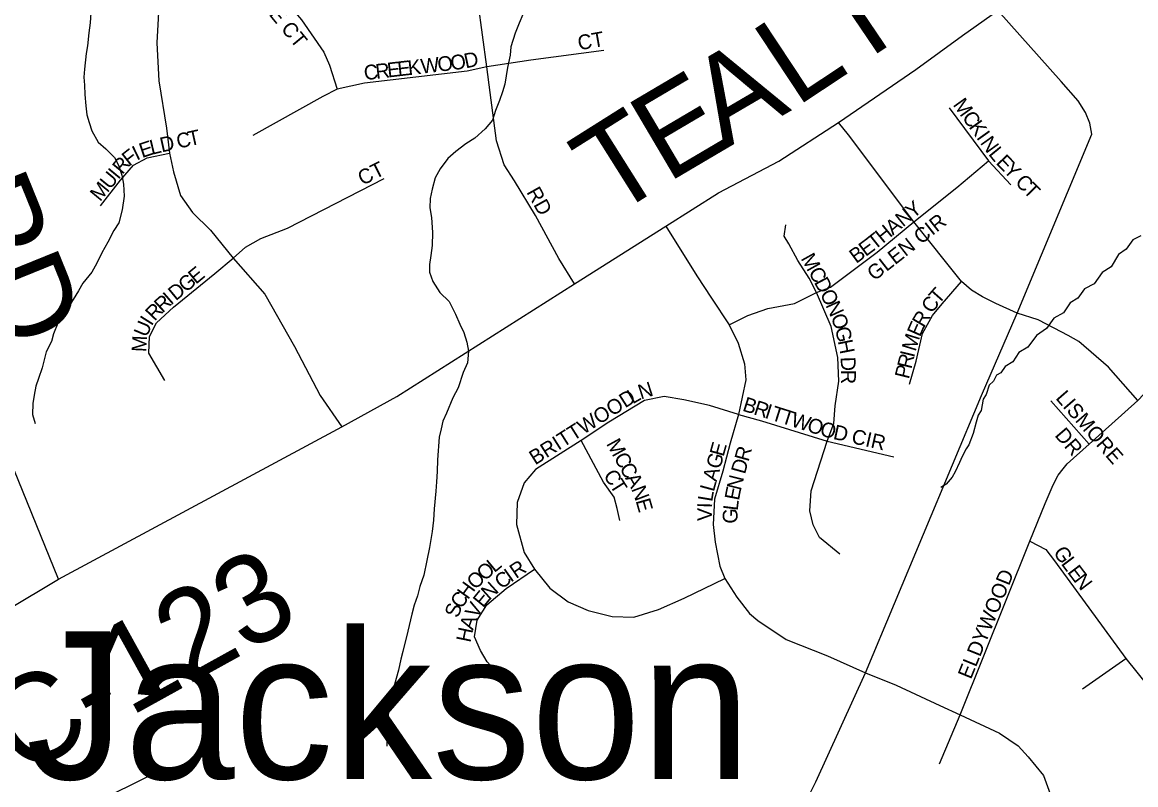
# Model space of a CAD drawing. Extents: x 1310247 to 1664935, y 235267 to 584339.
# Drawn here: x 1471939 to 1475707, y 405864 to 408445 of the extents above; entities that cross this region are included whole.
import ezdxf

# ---------------------------------------------------------------- set-up
doc = ezdxf.new("R2010")
doc.units = 0
for name, color, linetype in [('GM_X_County_Road', 7, 'Continuous'), ('GM_X_County_Road_Text', 7, 'Continuous'), ('GM_X_Minor_Lake_Text', 7, 'Continuous'), ('GM_X_Minor_River', 7, 'Continuous'), ('GM_X_Township_Road', 7, 'Continuous'), ('GM_X_Township_Road_Text', 7, 'Continuous'), ('GM_X_Township_Subdivision', 7, 'Continuous'), ('GM_X_Township_Subdivision_Text', 7, 'Continuous')]:
    doc.layers.add(name, color=color, linetype=linetype)

msp = doc.modelspace()

# ---------------------------------------------------------------- linework, layer by layer
at = {"layer": 'GM_X_County_Road'}
msp.add_lwpolyline([(1469618.3, 405075.7), (1469723.7, 405193), (1469936.4, 405367.3), (1470080.1, 405482.1), (1470194.3, 405541.7), (1470349.5, 405630.1), (1470505.2, 405715.2), (1470749, 405849.7), (1470814, 405888), (1471061, 406020.1), (1471335.2, 406154.1), (1471420.3, 406197.5), (1471890.1, 406457.8), (1472061.8, 406560), (1473020.6, 407075.3), (1473206.7, 407178.8), (1473808.4, 407559.6), (1474117, 407754.9), (1474295.5, 407867.9), (1474499.6, 407974.6), (1474701.1, 408105.8), (1474962.6, 408285.4), (1475121.3, 408399.8), (1475239.9, 408484.7)], dxfattribs=at)
at = {"layer": 'GM_X_Minor_River'}
for points in [[(1472171.6, 408477.1), (1472169, 408443), (1472164.4, 408409), (1472159.7, 408364.9), (1472155.2, 408338.9), (1472150.3, 408286.7), (1472147.8, 408258.6), (1472149.4, 408232.5), (1472150.9, 408200.3), (1472154.2, 408162.1), (1472157.7, 408132), (1472165.3, 408105.7), (1472174.9, 408077.4), (1472196.3, 408038.9), (1472222, 408016.3), (1472251.7, 407987.7), (1472265.3, 407961.4), (1472276.7, 407927), (1472282.2, 407896.8), (1472283.6, 407856.6), (1472276.8, 407810.5), (1472266, 407766.5), (1472249.5, 407740.7), (1472228.8, 407700.9), (1472208.1, 407665.1), (1472191.4, 407629.3), (1472174.9, 407599.4), (1472144.1, 407561.8), (1472129.6, 407536), (1472088.3, 407468.4), (1472059.5, 407426.7), (1472044.9, 407390.8), (1472038.4, 407364.8), (1472019.7, 407329), (1472006.8, 407275), (1471994.1, 407239.1), (1471985.7, 407213.1), (1471979.1, 407183.1), (1471974.6, 407155.1), (1471974, 407116.9), (1471983.5, 407086.6)], [(1473632.9, 408471.6), (1473620.3, 408441.7), (1473607.7, 408407.8), (1473592.9, 408361.9), (1473590.4, 408333.8), (1473581.7, 408291.8), (1473572.7, 408235.7), (1473564.2, 408209.7), (1473553.7, 408179.8), (1473541.1, 408145.9), (1473530.5, 408113.9), (1473505.9, 408084.2), (1473471.2, 408052.7), (1473440.8, 408033.1), (1473406.2, 408007.6), (1473379.7, 407984), (1473353, 407948.3), (1473336.5, 407918.5)], [(1473336.5, 407918.5), (1473325.8, 407880.5), (1473319.2, 407848.5), (1473318.7, 407816.4), (1473324.2, 407784.1), (1473327.3, 407733.9), (1473326.6, 407689.7), (1473322, 407655.6), (1473317.5, 407625.6), (1473317, 407599.5), (1473328.5, 407567.2), (1473352, 407530.6), (1473383.6, 407499.9), (1473405, 407457.4), (1473420.4, 407423), (1473434, 407394.6), (1473443.5, 407362.3), (1473449, 407332.1), (1473446.3, 407292), (1473431.8, 407260.1), (1473414.8, 407208.1), (1473396.2, 407174.3), (1473375.2, 407122.5), (1473362.7, 407094.6), (1473356.3, 407068.6), (1473349.8, 407040.6), (1473344.5, 406964.4), (1473343.8, 406924.2), (1473341.2, 406890.1), (1473338.7, 406858), (1473333.6, 406797.9), (1473331, 406759.7), (1473326.3, 406721.7), (1473317.4, 406667.6), (1473308.6, 406623.6), (1473297.7, 406573.5), (1473285, 406535.6), (1473276.5, 406503.6), (1473265.9, 406471.7), (1473257.3, 406441.7), (1473244.3, 406383.7), (1473227.1, 406315.7), (1473220.7, 406289.7), (1473212, 406251.7), (1473199.1, 406203.7), (1473190.6, 406173.8), (1473179.9, 406131.8), (1473177.2, 406095.7), (1473172.7, 406065.6), (1473172.3, 406039.5), (1473173.5, 405995.3)], [(1475723.9, 407722), (1475697.6, 407708.4), (1475675, 407676.7), (1475648.6, 407659.1), (1475623.8, 407617.3), (1475593.4, 407597.8), (1475566.6, 407560.1), (1475534.2, 407542.6), (1475511.6, 407510.8), (1475485.2, 407495.2), (1475462.6, 407461.5), (1475430.2, 407444), (1475405.5, 407408.2), (1475371, 407384.8), (1475342.2, 407345.1), (1475311.8, 407327.5), (1475291.2, 407295.8), (1475264.8, 407280.2), (1475250.4, 407258.3), (1475236.2, 407250.5), (1475225.8, 407230.6), (1475211.6, 407216.8), (1475201, 407184.9), (1475190.7, 407169), (1475184, 407131), (1475173.7, 407115.1), (1475167.3, 407091.1), (1475156.6, 407053.1), (1475141.9, 407015.2), (1475133.6, 407001.3), (1475119.2, 406975.4), (1475110.8, 406955.5), (1475096.2, 406923.6), (1475085.9, 406905.7), (1475065.4, 406882), (1475047.1, 406870.3)]]:
    msp.add_lwpolyline(points, dxfattribs=at)
at = {"layer": 'GM_X_Township_Road'}
for points in [[(1474001.2, 405348.9), (1474008.6, 405355.7), (1474087.4, 405426.5), (1474143.2, 405476.4), (1474257.7, 405560.6), (1474396.4, 405661.3), (1474492.3, 405732.9), (1474542.3, 405773.9), (1474601.5, 405828.6), (1474624.4, 405874.5), (1474792.2, 406243.1), (1475185.1, 407181.4), (1475305.4, 407460.8), (1475558.2, 408066.7), (1475552.2, 408102.9), (1475537.1, 408139.9), (1475512.2, 408179.2), (1475454.8, 408244.9), (1475239.9, 408484.7)], [(1472061.8, 406560), (1471790.3, 407226.9), (1471622.4, 407631), (1471514.1, 407906), (1471466.6, 408026.5), (1471422.8, 408130), (1471380.2, 408195.7), (1471301.1, 408289.4), (1471220.7, 408351.5), (1471027.5, 408456.4)]]:
    msp.add_lwpolyline(points, dxfattribs=at)
at = {"layer": 'GM_X_Township_Subdivision'}
for points in [[(1473808.4, 407559.6), (1473754.4, 407645.4), (1473675.9, 407790.9), (1473604.6, 407908.8), (1473569.7, 407962.6), (1473543.5, 408044), (1473523.1, 408207), (1473511.5, 408294.3), (1473482.4, 408511), (1473467.8, 408591), (1473451.8, 408674), (1473421.3, 408748.1), (1473387.8, 408822.3), (1473360.2, 408879), (1473313.6, 408937.2), (1473121.6, 409140.9), (1472898.3, 409373.6), (1472689.5, 409589), (1472650.3, 409644.2), (1472628.5, 409683.5), (1472619.7, 409760.6), (1472632, 409830.4)], [(1472898.3, 409373.6), (1472806.3, 409287.1), (1472675.4, 409161.6), (1472560.7, 409056.6), (1472513.1, 409009), (1472463.4, 408939.8), (1472432.4, 408839.8), (1472419.2, 408773.9), (1472411.7, 408685.8), (1472394.2, 408375.5), (1472400.9, 408246.8), (1472427.3, 408086.6), (1472437.7, 408001.8), (1472450.9, 407938.7), (1472474.4, 407858.6), (1472514.9, 407801.1), (1472576.2, 407740.9), (1472653.4, 407646.6), (1472759.9, 407525.1), (1472860.7, 407347), (1472947.3, 407181.9), (1473020.6, 407075.3)], [(1472720.1, 408644.9), (1472884.5, 408452.8), (1472959.7, 408343.8), (1472978.9, 408299.4), (1473004.4, 408218.4)], [(1473907.2, 408349.5), (1473659.8, 408316.1), (1473511.5, 408294.3), (1473444.7, 408279.5), (1473097.8, 408239), (1473004.4, 408218.4), (1472956.8, 408193.6), (1472719.6, 408062)], [(1475076.3, 408155), (1475209.2, 407976), (1475284.2, 407894.3)], [(1475305.4, 407460.8), (1475233.6, 407492.9), (1475189.1, 407515.5), (1475151.6, 407538.1), (1475118, 407567), (1474956.1, 407770), (1474735.4, 408064.4), (1474701.1, 408105.8)], [(1472203.7, 407823.7), (1472272.2, 407910.4), (1472315.9, 407960.8), (1472362.2, 407985.6), (1472437.7, 408001.8)], [(1474331.7, 407420.4), (1474394, 407452), (1474462, 407476.2), (1474551.9, 407492.7), (1474627, 407530.4), (1474674.6, 407548.6), (1474832.6, 407666.3), (1474956.1, 407770), (1475101.9, 407886.1), (1475209.2, 407976)], [(1472421.7, 407233), (1472368, 407325.4), (1472369.8, 407381.9), (1472393.4, 407428.1), (1472450.9, 407480.8), (1472591.2, 407594.8), (1472653.4, 407646.6), (1472694.9, 407683.4), (1472746.7, 407713.5), (1472837.1, 407748.4), (1473164, 407916.1)], [(1474117, 407754.9), (1474221.7, 407586.5), (1474271.4, 407511), (1474331.7, 407420.4), (1474361.7, 407359), (1474382.8, 407288.8), (1474388, 407234.4), (1474362.9, 407117), (1474335, 407020), (1474309.7, 406926.1), (1474282, 406830.9), (1474277.2, 406745.4), (1474283.8, 406685.8), (1474300.1, 406604.5), (1474316.9, 406562.4), (1474357.3, 406499.2), (1474400, 406443.8), (1474428.3, 406419.7), (1474523.9, 406356.2), (1474664.6, 406300.9), (1474792.2, 406243.1), (1474896.1, 406201), (1475044.7, 406132.6), (1475113.1, 406101), (1475245.9, 406039.2), (1475309.1, 405995.8), (1475343.2, 405959), (1475394.5, 405895.8), (1475435.3, 405784)], [(1474705.9, 406644.3), (1474637.3, 406700.9), (1474615.6, 406744.2), (1474604.8, 406791.2), (1474608.4, 406858.6), (1474662.6, 407027.3), (1474685.5, 407087.5), (1474690.3, 407146.5), (1474702.3, 407230.8), (1474698.7, 407310.3), (1474676.5, 407415.3), (1474627, 407530.4), (1474601.5, 407578.6), (1474563.6, 407638.7), (1474532.8, 407695.5), (1474517.8, 407721.5), (1474522.6, 407759.4)], [(1474941.3, 407220.5), (1474963.8, 407297.6), (1474986.1, 407391.3), (1475019.7, 407453), (1475051.8, 407491.7), (1475118, 407567)], [(1475713.9, 407165.3), (1475615.4, 407277.3), (1475514.7, 407364), (1475478, 407384.3), (1475431.1, 407409.3), (1475376.4, 407437.4), (1475305.4, 407460.8)], [(1475113.1, 406101), (1475348.7, 406688.8), (1475400.8, 406816.5), (1475427.2, 406879.7), (1475445, 406911.8), (1475461.1, 406933.4), (1475475.6, 406950.2), (1475549.9, 407017.3), (1475713.9, 407165.3), (1475793.9, 407249.4), (1475880, 407324.9)], [(1474362.9, 407117), (1474265.1, 407147.7), (1474178.4, 407167), (1474111, 407177.8), (1474044.8, 407164.5), (1473924.3, 407091.1), (1473830.4, 407029.7), (1473676.2, 406930.9), (1473637.7, 406886.4), (1473613.6, 406820.1), (1473611.2, 406745.4), (1473637.7, 406650.3), (1473672.6, 406593.7), (1473724.4, 406529.9), (1473787, 406482.9), (1473854.5, 406454), (1473935.2, 406433.5), (1474008.6, 406431.1), (1474091.7, 406457.6), (1474179.6, 406496.1), (1474316.9, 406562.4)], [(1475420.1, 407163.3), (1475549.9, 407017.3)], [(1474362.9, 407117), (1474441, 407095.9), (1474662.6, 407027.3), (1474889, 406974.3)], [(1473961.7, 406758.7), (1473952, 406799.6), (1473942.4, 406838.2), (1473906.3, 406888.8), (1473830.4, 407029.7)], [(1475348.7, 406688.8), (1475402.8, 406660.7), (1475432.6, 406622.7), (1475673.2, 406291.3), (1475818.3, 406111.8), (1476048.3, 405789.8), (1476182.4, 405651.7), (1476253.5, 405568.7), (1476314.4, 405461.3)], [(1473557, 406232.4), (1473512.4, 406280.6), (1473489.6, 406319.1), (1473469.2, 406364.6), (1473478.7, 406421.5), (1473511.2, 406473.3), (1473576.3, 406528.6), (1473672.6, 406593.7)], [(1475527.2, 406188.7), (1475673.2, 406291.3)], [(1475043.4, 405935.6), (1475113.1, 406101)], [(1472060.1, 405705.4), (1472050.6, 405736.3), (1472362.5, 405891.2)]]:
    msp.add_lwpolyline(points, dxfattribs=at)

# ---------------------------------------------------------------- texts
at = {"layer": 'GM_X_County_Road_Text'}
for s, rotation, p in [('T', 34.1193, (1474747.4, 408281.4)), ('L', 33.4852, (1474557.2, 408155.6)), ('A', 30.3684, (1474314.3, 408012.7)), ('E', 30.5433, (1474121.3, 407898.8)), ('T', 32.2303, (1473933.5, 407780.3)), ('C-123', 28.9506, (1471933.1, 405888.5))]:
    msp.add_text(s, height=300, rotation=rotation, dxfattribs=at).set_placement(p)
at = {"layer": 'GM_X_Minor_Lake_Text'}
msp.add_text('Jackson', height=499.99, rotation=0.0001, dxfattribs=at).set_placement((1471951.6, 405883.5))
at = {"layer": 'GM_X_Township_Road_Text'}
msp.add_text('RD', height=300, rotation=292.0722, dxfattribs=at).set_placement((1471661.1, 407857.4))
at = {"layer": 'GM_X_Township_Subdivision_Text'}
for s, rotation, p in [('RIDGE CT', 309.4798, (1472665.8, 408600)), ('CT', 10.0138, (1473823.4, 408349.9)), ('E', 6.5151, (1473176.7, 408257.8)), ('E', 6.5214, (1473211.6, 408261.8)), ('K', 6.5401, (1473246.6, 408265.7)), ('W', 6.5203, (1473290.3, 408270.8)), ('O', 6.5285, (1473347.2, 408277.3)), ('O', 7.04, (1473391.4, 408282.3)), ('D', 12.1856, (1473439.9, 408288.5)), ('C', 6.5226, (1473098, 408248.7)), ('R', 6.532, (1473137.3, 408253.2)), ('M', 305.5948, (1475086.7, 408165.7)), ('C', 305.5828, (1475117.4, 408122.7)), ('K', 305.5758, (1475140.5, 408090.5)), ('L', 13.6519, (1472377.1, 407996)), ('D', 12.5359, (1472411, 408004.3)), ('C', 12.5325, (1472466.9, 408016.7)), ('T', 12.5318, (1472505.5, 408025.3)), ('I', 305.5792, (1475166.1, 408054.7)), ('N', 305.5993, (1475178.9, 408036.8)), ('F', 38.0667, (1472301.2, 407956)), ('I', 25.7245, (1472326.5, 407976.2)), ('E', 18.5127, (1472344.8, 407985.1)), ('L', 309.2603, (1475206.6, 407998.3)), ('R', 50.5498, (1472278.1, 407927.4)), ('CT', 26.565, (1473090.4, 407891.4)), ('E', 313.7851, (1475231.8, 407967.8)), ('Y', 314.1072, (1475256.3, 407942.2)), ('U', 50.5414, (1472236.1, 407876.5)), ('I', 50.5438, (1472264.1, 407910.4)), ('M', 50.5466, (1472202.6, 407835.7)), ('C', 314.098, (1475296.1, 407901.1)), ('T', 314.0918, (1475323.7, 407872.6)), ('RD', 299.361, (1473644, 407870)), ('Y', 39.1956, (1474953.3, 407778)), ('GLEN CIR', 38.1104, (1474822.6, 407567.4)), ('N', 39.2164, (1474919.2, 407750.2)), ('H', 39.1847, (1474851, 407694.6)), ('A', 39.2164, (1474885.1, 407722.4)), ('E', 36.6217, (1474793.2, 407650.2)), ('T', 38.3611, (1474822.8, 407672.2)), ('B', 36.3308, (1474761.1, 407626.6)), ('M', 299.1891, (1474572.3, 407645.8)), ('E', 39.6212, (1472526.6, 407556.3)), ('C', 299.1728, (1474598.1, 407599.7)), ('D', 39.7076, (1472458.8, 407500.2)), ('G', 39.5985, (1472492.6, 407528.3)), ('D', 298.0121, (1474617.3, 407565.4)), ('R', 42.4403, (1472413.5, 407459.4)), ('I', 41.0708, (1472442.5, 407485.9)), ('O', 295.1674, (1474637.6, 407527.1)), ('T', 48.5185, (1475039.9, 407488.1)), ('R', 46.46, (1472386.9, 407431.4)), ('N', 294.5019, (1474656.3, 407487.4)), ('C', 55.2726, (1475018.3, 407456.8)), ('I', 57.6193, (1472376.7, 407414.8)), ('O', 290.5919, (1474674.2, 407448.2)), ('R', 59.6492, (1474990.3, 407408.6)), ('U', 67.1716, (1472360.6, 407376.2)), ('G', 282.6473, (1474689.1, 407408.8)), ('E', 66.3192, (1474976.9, 407377.7)), ('M', 87.3577, (1472359.2, 407328)), ('H', 281.0184, (1474698.7, 407366.2)), ('M', 72.9893, (1474961.9, 407328.6)), ('I', 76.3243, (1474956.9, 407308)), ('D', 271.9456, (1474708.5, 407312)), ('R', 76.3243, (1474947.6, 407269.5)), ('R', 270, (1474710, 407268.5)), ('P', 76.3243, (1474939.3, 407235.3)), ('N', 17.5848, (1474032.4, 407167.9)), ('BRITTWOOD', 32.3693, (1473674.9, 406945)), ('L', 29.7923, (1474004.4, 407151.5)), ('LISMORE', 311.0089, (1475433.7, 407172)), ('B', 342.3867, (1474373.5, 407130.8)), ('R', 342.3562, (1474411.2, 407118.8)), ('I', 342.3831, (1474449, 407106.8)), ('T', 342.3771, (1474469.9, 407100.1)), ('T', 342.3771, (1474503.5, 407089.5)), ('W', 342.3732, (1474537.1, 407078.8)), ('O', 342.3669, (1474591.6, 407061.5)), ('O', 344.3315, (1474635.3, 407047.6)), ('D', 347.6971, (1474680.8, 407035)), ('CIR', 347.1949, (1474742.3, 407021)), ('DR', 310.6039, (1475430.8, 407046.1)), ('M', 298.7486, (1473914.2, 407018.6)), ('E', 74.4027, (1474312.2, 406972.5)), ('R', 74.5149, (1474396.4, 406955.6)), ('C', 298.7597, (1473939.6, 406972.3)), ('G', 74.3998, (1474300.4, 406930.1)), ('D', 74.5589, (1474384.7, 406913.2)), ('C', 302.8885, (1473903.8, 406911.4)), ('C', 298.7597, (1473958.7, 406937.6)), ('A', 74.4209, (1474288.6, 406887.7)), ('T', 302.4167, (1473925.2, 406878.2)), ('A', 299.833, (1473978.2, 406902)), ('N', 290.7582, (1473999.2, 406865.7)), ('L', 74.824, (1474279.4, 406853.8)), ('N', 76.1175, (1474370.8, 406858.1)), ('L', 80.5871, (1474273.9, 406820.4)), ('E', 78.808, (1474364.1, 406824.2)), ('E', 285.9379, (1474014.4, 406825.6)), ('I', 88.3384, (1474273.5, 406800.2)), ('L', 82.9597, (1474359.9, 406790.2)), ('V', 89.6721, (1474273.2, 406756.5)), ('G', 88.9727, (1474359.2, 406747.6)), ('G', 304.1022, (1475426.3, 406650.8)), ('L', 39.3298, (1473536.6, 406580.2)), ('R', 33.9932, (1473610.1, 406560.3)), ('L', 306.8751, (1475452.5, 406612.2)), ('O', 42.7279, (1473471.5, 406522.2)), ('O', 40.561, (1473503.4, 406551.8)), ('C', 37.3702, (1473561.3, 406524)), ('I', 35.2785, (1473592.4, 406547.7)), ('ELDYWOOD', 67.9322, (1475149.5, 406218.9)), ('E', 307.2188, (1475473.8, 406583.8)), ('N', 307.2344, (1475495.1, 406555.8)), ('H', 53.9924, (1473447.3, 406488.6)), ('N', 42.0928, (1473519.5, 406486.6)), ('C', 53.9851, (1473424, 406456.6)), ('E', 50.824, (1473498.7, 406460.7)), ('S', 71.1935, (1473414.5, 406426.7)), ('V', 59.9434, (1473477.8, 406424.4)), ('A', 70.8461, (1473464.4, 406385.1)), ('H', 78.3128, (1473456, 406343.7))]:
    msp.add_text(s, height=50, rotation=rotation, dxfattribs=at).set_placement(p)

doc.saveas('drawing.dxf')
